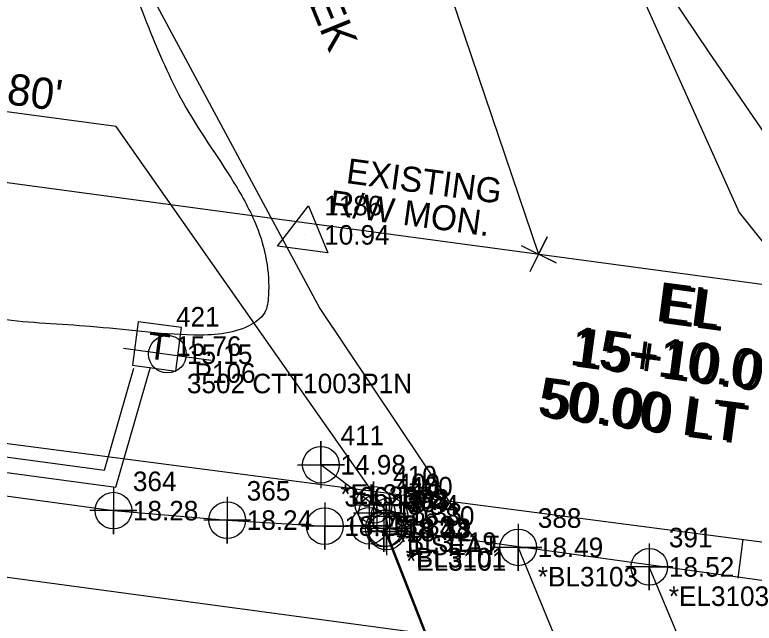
# Model space of a CAD drawing. Extents: x 2627243 to 2636458, y 566398 to 571062.
# Drawn here: x 2634518 to 2634612.5, y 569107.7 to 569185.6 of the extents above; entities that cross this region are included whole.
import ezdxf

# ---------------------------------------------------------------- set-up
doc = ezdxf.new("R2010")
doc.units = 0
for name, color, linetype in [('COGO Default Chain', 7, 'Continuous'), ('Exist Horizontal Alignment', 7, 'Continuous'), ('Exist Horizontal Baseline Alignment', 7, 'Continuous'), ('Exist Horizontal Baseline Alignment Tick small', 7, 'Continuous'), ('Exist Hydro Jurisdictional Stream or Body of Water', 7, 'Continuous'), ('Exist Hydro Jurisdictional Stream or Body of Water Text', 7, 'Continuous'), ('Exist Property Corner CELL', 7, 'Continuous'), ('Exist Property Line', 7, 'Continuous'), ('Exist Right of Way Line', 7, 'Continuous'), ('Exist Right of Way Monument CELL', 7, 'Continuous'), ('Exist Right of Way Monument Cogo Elevation', 7, 'Continuous'), ('Exist Right of Way Monument Cogo Number', 7, 'Continuous'), ('Exist Right of Way Monument Text', 7, 'Continuous'), ('Exist Roads EOP', 7, 'Continuous'), ('Exist Roads EOP Cogo Elevation', 7, 'Continuous'), ('Exist Roads EOP Cogo Number', 7, 'Continuous'), ('Exist Roads EOP Cogo Point CELL', 7, 'Continuous'), ('Exist Structure Major Bridge Seam', 7, 'Continuous'), ('Exist Structure Major Bridge Seam Cogo Comment', 7, 'Continuous'), ('Exist Structure Major Bridge Seam Cogo Elevation', 7, 'Continuous'), ('Exist Structure Major Bridge Seam Cogo Number', 7, 'Continuous'), ('Exist Structure Major Bridge Seam Cogo Point CELL', 7, 'Continuous'), ('Exist Structure Major Bridge Seat Cogo Comment', 7, 'Continuous'), ('Exist Structure Major Bridge Seat Cogo Elevation', 7, 'Continuous'), ('Exist Structure Major Bridge Seat Cogo Number', 7, 'Continuous'), ('Exist Structure Major Bridge Seat Cogo Point CELL', 7, 'Continuous'), ('Exist Structure Major Bridge Seat Top Elevation', 7, 'Continuous'), ('Exist Structure Major Bridge WW', 7, 'Continuous'), ('Exist Structure Major Bridge WW Cogo Comment', 7, 'Continuous'), ('Exist Structure Major Bridge WW Cogo Elevation', 7, 'Continuous'), ('Exist Structure Major Bridge WW Cogo Number', 7, 'Continuous'), ('Exist Structure Major Bridge WW Cogo Point CELL', 7, 'Continuous'), ('Exist Structure Major Deck Tunnel Box Culvert', 7, 'Continuous'), ('Exist Structure Major Deck Tunnel Box Culvert Cogo Comment', 7, 'Continuous'), ('Exist Structure Major Deck Tunnel Box Culvert Cogo Elevation', 7, 'Continuous'), ('Exist Structure Major Deck Tunnel Box Culvert Cogo Number', 7, 'Continuous'), ('Exist Structure Major Deck Tunnel Box Culvert Cogo Point CELL', 7, 'Continuous'), ('Exist Utilities Telephone Pedestal CELL', 7, 'Continuous'), ('Exist Utilities Telephone Pedestal Cogo Elevation', 7, 'Continuous'), ('Exist Utilities Telephone Pedestal Cogo Number', 7, 'Continuous'), ('Exist Utilities Telephone Pole CELL', 7, 'Continuous'), ('Exist Utilities Telephone Pole Cogo Comment', 7, 'Continuous'), ('Exist Utilities Telephone Pole Cogo Elevation', 7, 'Continuous'), ('Exist Utilities Telephone Pole Cogo Number', 7, 'Continuous'), ('Exist Utilities Telephone UG Cable', 7, 'Continuous'), ('Exist Vegetation Woods Line', 7, 'Continuous'), ('Scratch_Level_1', 7, 'Continuous'), ('Scratch_Level_2', 7, 'Continuous')]:
    doc.layers.add(name, color=color, linetype=linetype)

# ---------------------------------------------------------------- blocks, each defined once
blk = doc.blocks.new('EXIST ROADS EOP COGO POINT')
at = {"layer": 'Exist Roads EOP Cogo Point CELL'}
blk.add_lwpolyline([(0, 0.06), (0, -0.06), (0, 0), (0.06, 0), (-0.06, 0)], dxfattribs=at)
blk.add_circle((0, 0), 0.0469, dxfattribs=at)
blk = doc.blocks.new('EXIST STRUCTURE MAJOR DECK TUNNEL BOX CULVERT COGO POINT')
at = {"layer": 'Exist Structure Major Deck Tunnel Box Culvert Cogo Point CELL'}
blk.add_lwpolyline([(-0.06, 0), (0.06, 0), (0, 0), (0, 0.06), (0, -0.06)], dxfattribs=at)
blk.add_circle((0, 0), 0.0469, dxfattribs=at)
blk = doc.blocks.new('EXIST BRIDGE SEAM COGO POINT')
at = {"layer": 'Exist Structure Major Bridge Seam Cogo Point CELL'}
blk.add_lwpolyline([(0, 0.06), (0, -0.06), (0, 0), (0.06, 0), (-0.06, 0)], dxfattribs=at)
blk.add_circle((0, 0), 0.0469, dxfattribs=at)
blk = doc.blocks.new('EXIST STRUCTURE MAJOR BRIDGE SEAT COGO POINT')
at = {"layer": 'Exist Structure Major Bridge Seat Cogo Point CELL'}
blk.add_lwpolyline([(-0.06, 0), (0.06, 0), (0, 0), (0, 0.06), (0, -0.06)], dxfattribs=at)
blk.add_circle((0, 0), 0.0469, dxfattribs=at)
blk = doc.blocks.new('EXIST STRUCTURE MAJOR BRIDGE WW COGO POINT')
at = {"layer": 'Exist Structure Major Bridge WW Cogo Point CELL'}
blk.add_lwpolyline([(-0.06, 0), (0.06, 0), (0, 0), (0, 0.06), (0, -0.06)], dxfattribs=at)
blk.add_circle((0, 0), 0.0469, dxfattribs=at)
blk = doc.blocks.new('EXIST UTILITIES TELEPHONE PEDESTAL')
at = {"layer": 'Exist Utilities Telephone Pedestal CELL'}
blk.add_line((0, 0), (0, 0), dxfattribs=at)
blk.add_lwpolyline([(-0.0545, -0.0565), (0.0574, -0.0565), (0.0574, 0.0554), (-0.0545, 0.0554), (-0.0545, -0.0565)], dxfattribs=at)
blk.add_text('T', height=0.0684, dxfattribs=at).set_placement((-0.0226, -0.0343))
blk = doc.blocks.new('EXIST UTILITIES TELEPHONE POLE')
at = {"layer": 'Exist Utilities Telephone Pole CELL'}
for p, q in [((-0.1135, 0), (0.11325, 0)), ((0, 0), (0, 0))]:
    blk.add_line(p, q, dxfattribs=at)
blk.add_circle((0, 0), 0.04813, dxfattribs=at)
blk = doc.blocks.new('EXIST RIGHT OF WAY MONUMENT')
at = {"layer": 'Exist Right of Way Monument CELL'}
blk.add_line((0, 0), (0, 0), dxfattribs=at)
blk.add_lwpolyline([(-0.065, -0.0378), (0, 0.075), (0.065, -0.0378)], close=True, dxfattribs=at)

msp = doc.modelspace()

# ---------------------------------------------------------------- linework, layer by layer
at = {"layer": 'COGO Default Chain'}
msp.add_line((2634072.78, 569173.542), (2634872.745, 569065.698), dxfattribs=at)
msp.add_line((2634072.78, 569173.542), (2634872.745, 569065.698), dxfattribs=at)
at = {"layer": 'Exist Horizontal Alignment'}
msp.add_line((2634072.78, 569173.542), (2634872.745, 569065.698), dxfattribs=at)
at = {"layer": 'Exist Horizontal Baseline Alignment'}
msp.add_line((2634115.269, 569183.035), (2634680.61, 569109.426), dxfattribs=at)
at = {"layer": 'Exist Horizontal Baseline Alignment Tick small'}
msp.add_line((2634611.083, 569118.479), (2634610.438, 569113.52), dxfattribs=at)
at = {"layer": 'Exist Hydro Jurisdictional Stream or Body of Water'}
for points in [[(2634586.407, 569214.214), (2634610.63, 569160.296), (2634652.537, 569107.83)], [(2634535.261, 569188.384), (2634556.98, 569147.996), (2634576.873, 569118.308)]]:
    msp.add_lwpolyline(points, dxfattribs=at)
at = {"layer": 'Exist Property Corner CELL'}
msp.add_line((2634584.961, 569154.947), (2634584.961, 569154.947), dxfattribs=at)
msp.add_lwpolyline([(2634582.72, 569156.054), (2634587.202, 569153.839), (2634584.961, 569154.947), (2634586.069, 569157.188), (2634583.853, 569152.705)], dxfattribs=at)
at = {"layer": 'Exist Property Line'}
msp.add_line((2634568.743, 569202.857), (2634584.961, 569154.947), dxfattribs=at)
at = {"layer": 'Exist Right of Way Line'}
msp.add_line((2632427.744, 569445.763), (2634879.425, 569115.25), dxfattribs=at)
at = {"layer": 'Exist Roads EOP'}
msp.add_lwpolyline([(2634467.061, 569130.692), (2634503.954, 569125.774), (2634530.576, 569122.144), (2634545.134, 569120.932), (2634557.62, 569120.167), (2634563.301, 569120.217), (2634565.155, 569119.865), (2634575.95, 569092.263), (2634569.43, 569093.614), (2634553.414, 569096.958), (2634517.197, 569102.627), (2634476.746, 569107.617), (2634427.927, 569114.34)], dxfattribs=at)
at = {"layer": 'Exist Structure Major Bridge Seam'}
for p, q in [((2634582.37, 569117.451), (2634593.704, 569089.767)), ((2634610.676, 569087.421), (2634599.129, 569114.954))]:
    msp.add_line(p, q, dxfattribs=at)
at = {"layer": 'Exist Structure Major Bridge Seat Top Elevation'}
msp.add_lwpolyline([(2634565.897, 569121.455), (2634530.914, 569171.294), (2634491.167, 569176.631)], dxfattribs=at)
at = {"layer": 'Exist Structure Major Bridge WW'}
msp.add_lwpolyline([(2634564.295, 569121.869), (2634563.865, 569122.878), (2634557.123, 569128.014)], dxfattribs=at)
at = {"layer": 'Exist Structure Major Deck Tunnel Box Culvert'}
msp.add_lwpolyline([(2634565.456, 569119.889), (2634666.463, 569105.901), (2634677.512, 569078.102), (2634576.153, 569092.129), (2634565.524, 569119.463)], dxfattribs=at)
at = {"layer": 'Exist Utilities Telephone UG Cable'}
for points in [[(2633874.517, 569217.369), (2634467.736, 569135.646), (2634529.442, 569127.342), (2634533.196, 569140.365)], [(2633874.244, 569215.387), (2634467.466, 569133.665), (2634530.886, 569125.129), (2634535.277, 569140.365)]]:
    msp.add_lwpolyline(points, dxfattribs=at)
at = {"layer": 'Exist Vegetation Woods Line'}
msp.add_lwpolyline([(2634887.579, 569122.445), (2634875.665, 569121.098), (2634835.437, 569125.639), (2634775.479, 569133.301), (2634729.695, 569139.907), (2634669.529, 569148.147), (2634654.311, 569141.894), (2634645.02, 569138.697), (2634633.988, 569141.111), (2634606.763, 569180.82), (2634584.754, 569213.571), (2634568.049, 569253.913), (2634545.266, 569307.501)], dxfattribs=at)
msp.add_spline([(2634392.308, 569564.874), (2634393.363, 569560.608), (2634394.346, 569549.309), (2634394.022, 569537.8), (2634392.819, 569525.734), (2634391.567, 569515.693), (2634392.51, 569504.78), (2634393.838, 569497.809), (2634395.596, 569492.756), (2634400.875, 569483.764), (2634407.468, 569473.343), (2634412.267, 569464.458), (2634417.663, 569454.306), (2634422.98, 569444.927), (2634428.507, 569434.243), (2634432.459, 569422.15), (2634434.601, 569410.968), (2634437.501, 569399.237), (2634441.272, 569389.703), (2634445.91, 569380.099), (2634449.774, 569370.417), (2634453.453, 569361.03), (2634457.812, 569351.867), (2634462.968, 569341.769), (2634468.24, 569330.512), (2634473.087, 569319.602), (2634478.003, 569309.559), (2634483.701, 569297.954), (2634488.926, 569288.722), (2634494.899, 569280.581), (2634497.979, 569276.363), (2634502.493, 569265.654), (2634505.902, 569255.068), (2634509.62, 569245.294), (2634513.833, 569236.037), (2634518.323, 569226.341), (2634522.837, 569215.632), (2634527.245, 569204.444), (2634530.962, 569194.67), (2634535.09, 569183.922), (2634539.488, 569174.373), (2634545.989, 569164.098), (2634548.892, 569158.535), (2634550.414, 569149.633), (2634549.928, 569147.476), (2634547.913, 569145.789), (2634540.849, 569144.609), (2634527.623, 569145.695), (2634516.129, 569146.644), (2634503.907, 569149.393), (2634493.177, 569152.059), (2634481.311, 569153.595), (2634470.722, 569154.088), (2634458.152, 569156.412), (2634447.075, 569158.652), (2634435.874, 569159.787), (2634423.994, 569160.696), (2634414.046, 569161.801), (2634402.806, 569163.323), (2634392.711, 569164.334), (2634382.43, 569165.64), (2634371.245, 569167.4), (2634360.406, 569169.586), (2634350.141, 569171.518), (2634339.009, 569173.518), (2634328.303, 569175.171), (2634318.022, 569176.477), (2634307.609, 569178.315), (2634296.972, 569180.834), (2634285.801, 569183.221), (2634274.523, 569185.128), (2634263.244, 569187.036), (2634253.164, 569188.674), (2634241.646, 569190.635), (2634229.634, 569192.078), (2634218.433, 569193.213), (2634208.084, 569193.652), (2634195.005, 569194.832), (2634183.873, 569196.832), (2634172.688, 569198.593), (2634159.531, 569200.545), (2634149.157, 569201.998), (2634139.17, 569203.488), (2634124.428, 569205.672), (2634114.28, 569206.444), (2634101.371, 569206.704), (2634089.863, 569207.026), (2634085.093, 569207.092)], degree=3, dxfattribs=at)

# ---------------------------------------------------------------- block references
at = {"layer": 'Exist Right of Way Monument CELL', "xscale": 49.99999999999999, "yscale": 50, "rotation": -7.677818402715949}
msp.add_blockref('EXIST RIGHT OF WAY MONUMENT', (2634555.042, 569157.423), dxfattribs=at)
at = {"layer": 'Exist Roads EOP Cogo Point CELL', "xscale": 50, "yscale": 50}
for p in [(2634530.576, 569122.144), (2634545.134, 569120.932), (2634557.62, 569120.167), (2634563.301, 569120.217), (2634565.155, 569119.865)]:
    msp.add_blockref('EXIST ROADS EOP COGO POINT', p, dxfattribs=at)
at = {"layer": 'Exist Structure Major Bridge Seam Cogo Point CELL', "xscale": 50, "yscale": 50}
for p in [(2634582.37, 569117.451), (2634599.129, 569114.954)]:
    msp.add_blockref('EXIST BRIDGE SEAM COGO POINT', p, dxfattribs=at)
at = {"layer": 'Exist Structure Major Bridge Seat Cogo Point CELL', "xscale": 50, "yscale": 50}
msp.add_blockref('EXIST STRUCTURE MAJOR BRIDGE SEAT COGO POINT', (2634565.897, 569121.455), dxfattribs=at)
at = {"layer": 'Exist Structure Major Bridge WW Cogo Point CELL', "xscale": 50, "yscale": 50}
for p in [(2634557.123, 569128.014), (2634563.865, 569122.878), (2634564.295, 569121.869)]:
    msp.add_blockref('EXIST STRUCTURE MAJOR BRIDGE WW COGO POINT', p, dxfattribs=at)
at = {"layer": 'Exist Structure Major Deck Tunnel Box Culvert Cogo Point CELL', "xscale": 50, "yscale": 50}
for p in [(2634565.456, 569119.889), (2634565.524, 569119.463)]:
    msp.add_blockref('EXIST STRUCTURE MAJOR DECK TUNNEL BOX CULVERT COGO POINT', p, dxfattribs=at)
at = {"layer": 'Exist Utilities Telephone Pedestal CELL', "xscale": 50, "yscale": 50.00000000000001, "rotation": -7.677818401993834}
msp.add_blockref('EXIST UTILITIES TELEPHONE PEDESTAL', (2634536.092, 569143.191), dxfattribs=at)
at = {"layer": 'Exist Utilities Telephone Pole CELL', "xscale": 50, "yscale": 49.99999999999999, "rotation": -7.6778184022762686}
msp.add_blockref('EXIST UTILITIES TELEPHONE POLE', (2634537.489, 569142.161), dxfattribs=at)

# ---------------------------------------------------------------- texts
at = {"layer": 'Exist Hydro Jurisdictional Stream or Body of Water Text'}
msp.add_text('DURHAM CREEK', height=4, rotation=292.20855, dxfattribs=at).set_placement((2634541.833, 569220.753))
at = {"layer": 'Exist Right of Way Monument Cogo Elevation'}
msp.add_text('10.94', height=2.5, dxfattribs=at).set_placement((2634557.542, 569156.173))
at = {"layer": 'Exist Right of Way Monument Cogo Number'}
msp.add_text('1186', height=2.5, dxfattribs=at).set_placement((2634557.542, 569159.923))
at = {"layer": 'Exist Right of Way Monument Text'}
for s, p in [('EXISTING', (2634560.239, 569164.066)), ('R/W MON.', (2634558.055, 569159.998))]:
    msp.add_text(s, height=3.2, rotation=352.32218, dxfattribs=at).set_placement(p)
at = {"layer": 'Exist Roads EOP Cogo Elevation'}
for s, p in [('18.28', (2634533.076, 569120.894)), ('18.24', (2634547.634, 569119.682)), ('18.28', (2634560.12, 569118.917)), ('18.33', (2634565.801, 569118.967)), ('18.43', (2634567.655, 569118.615))]:
    msp.add_text(s, height=2.5, dxfattribs=at).set_placement(p)
at = {"layer": 'Exist Roads EOP Cogo Number'}
for s, p in [('364', (2634533.076, 569124.644)), ('365', (2634547.634, 569123.432)), ('366', (2634560.12, 569122.667)), ('367', (2634565.801, 569122.717)), ('368', (2634567.655, 569122.365))]:
    msp.add_text(s, height=2.5, dxfattribs=at).set_placement(p)
at = {"layer": 'Exist Structure Major Bridge Seam Cogo Comment'}
for s, p in [('*BL3103', (2634584.87, 569112.451)), ('*EL3103', (2634601.629, 569109.954))]:
    msp.add_text(s, height=2.5, dxfattribs=at).set_placement(p)
at = {"layer": 'Exist Structure Major Bridge Seam Cogo Elevation'}
for s, p in [('18.49', (2634584.87, 569116.201)), ('18.52', (2634601.629, 569113.704))]:
    msp.add_text(s, height=2.5, dxfattribs=at).set_placement(p)
at = {"layer": 'Exist Structure Major Bridge Seam Cogo Number'}
for s, p in [('388', (2634584.87, 569119.951)), ('391', (2634601.629, 569117.454))]:
    msp.add_text(s, height=2.5, dxfattribs=at).set_placement(p)
at = {"layer": 'Exist Structure Major Bridge Seat Cogo Comment'}
msp.add_text('1 SEAT', height=2.5, dxfattribs=at).set_placement((2634568.397, 569116.455))
at = {"layer": 'Exist Structure Major Bridge Seat Cogo Elevation'}
msp.add_text('16.80', height=2.5, dxfattribs=at).set_placement((2634568.397, 569120.205))
at = {"layer": 'Exist Structure Major Bridge Seat Cogo Number'}
msp.add_text('400', height=2.5, dxfattribs=at).set_placement((2634568.397, 569123.955))
at = {"layer": 'Exist Structure Major Bridge Seat Top Elevation'}
msp.add_text("SEAT=16.80'", height=4, rotation=352.11554, dxfattribs=at).set_placement((2634492.519, 569177.537))
at = {"layer": 'Exist Structure Major Bridge WW Cogo Comment'}
for s, p in [('*EL3119', (2634559.623, 569123.014)), ('*BL3119', (2634566.795, 569116.869))]:
    msp.add_text(s, height=2.5, dxfattribs=at).set_placement(p)
at = {"layer": 'Exist Structure Major Bridge WW Cogo Elevation'}
for s, p in [('14.98', (2634559.623, 569126.764)), ('18.34', (2634566.365, 569121.628)), ('18.33', (2634566.795, 569120.619))]:
    msp.add_text(s, height=2.5, dxfattribs=at).set_placement(p)
at = {"layer": 'Exist Structure Major Bridge WW Cogo Number'}
for s, p in [('411', (2634559.623, 569130.514)), ('410', (2634566.365, 569125.378)), ('409', (2634566.795, 569124.369))]:
    msp.add_text(s, height=2.5, dxfattribs=at).set_placement(p)
at = {"layer": 'Exist Structure Major Deck Tunnel Box Culvert Cogo Comment'}
for s, p in [('*BL3101', (2634567.956, 569114.889)), ('*EL3101', (2634568.024, 569114.463))]:
    msp.add_text(s, height=2.5, dxfattribs=at).set_placement(p)
at = {"layer": 'Exist Structure Major Deck Tunnel Box Culvert Cogo Elevation'}
for s, p in [('18.38', (2634567.956, 569118.639)), ('18.42', (2634568.024, 569118.213))]:
    msp.add_text(s, height=2.5, dxfattribs=at).set_placement(p)
at = {"layer": 'Exist Structure Major Deck Tunnel Box Culvert Cogo Number'}
for s, p in [('383', (2634567.956, 569122.389)), ('387', (2634568.024, 569121.963))]:
    msp.add_text(s, height=2.5, dxfattribs=at).set_placement(p)
at = {"layer": 'Exist Utilities Telephone Pedestal Cogo Elevation'}
msp.add_text('15.76', height=2.5, dxfattribs=at).set_placement((2634538.592, 569141.941))
at = {"layer": 'Exist Utilities Telephone Pedestal Cogo Number'}
msp.add_text('421', height=2.5, dxfattribs=at).set_placement((2634538.592, 569145.691))
at = {"layer": 'Exist Utilities Telephone Pole Cogo Comment'}
msp.add_text('3502 CTT1003P1N', height=2.5, dxfattribs=at).set_placement((2634539.989, 569137.161))
at = {"layer": 'Exist Utilities Telephone Pole Cogo Elevation'}
msp.add_text('15.15', height=2.5, dxfattribs=at).set_placement((2634539.989, 569140.911))
at = {"layer": 'Exist Utilities Telephone Pole Cogo Number'}
msp.add_text('P106', height=2.5, dxfattribs=at).set_placement((2634540.958, 569138.493))
at = {"layer": 'Scratch_Level_1'}
for s, p in [('EL', (2634600.372, 569146.207)), ('15+10.07', (2634589.332, 569140.632)), ('50.00 LT', (2634585.197, 569134.126))]:
    msp.add_text(s, height=5, rotation=352.32218, dxfattribs=at).set_placement(p)
at = {"layer": 'Scratch_Level_2'}
for s, p in [('EL', (2634599.815, 569146.449)), ('15+10.07', (2634588.799, 569140.824)), ('50.00 LT', (2634584.694, 569134.3))]:
    msp.add_text(s, height=5, rotation=352.58169, dxfattribs=at).set_placement(p)

doc.saveas('drawing.dxf')
